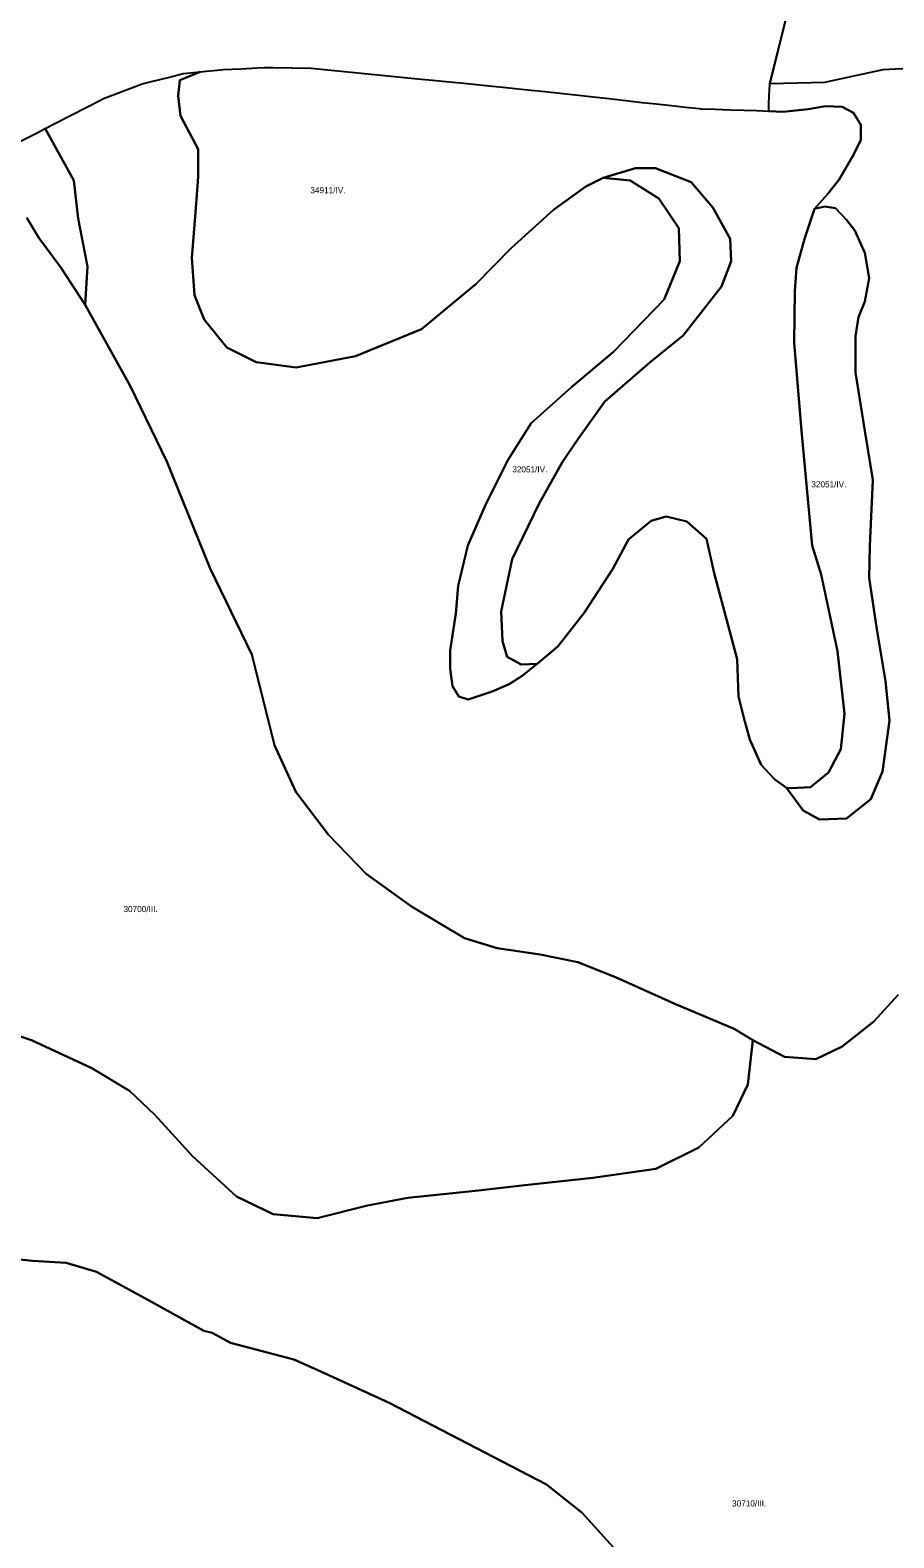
# Model space of a CAD drawing. Extents: x -521621 to -516761, y -1190184 to -1184927.
# Drawn here: x -521195 to -520631, y -1188092 to -1187109 of the extents above; entities that cross this region are included whole.
import ezdxf

# ---------------------------------------------------------------- set-up
doc = ezdxf.new("R2010")
doc.units = 0
doc.layers.add('BPEJ_s', color=7, linetype='Continuous')
doc.layers.add('odvodneni_s', color=7, linetype='Continuous')

msp = doc.modelspace()

# ---------------------------------------------------------------- linework, layer by layer
at = {"layer": 'BPEJ_s'}
for p, q in [((-520712.14, -1187143.85), (-520696.62, -1187081.22)), ((-521116.43, -1187142.72), (-521104.67, -1187139.74)), ((-521104.67, -1187139.74), (-521094.94, -1187137.28)), ((-521083.86, -1187136.13), (-521097.14, -1187141.62)), ((-521094.94, -1187137.28), (-521092.47, -1187137.03)), ((-521092.47, -1187137.03), (-521083.86, -1187136.13)), ((-521142.41, -1187151.9), (-521129.06, -1187146.84)), ((-521129.06, -1187146.84), (-521121.76, -1187144.07)), ((-521121.76, -1187144.07), (-521116.43, -1187142.72)), ((-521097.14, -1187141.62), (-521098.28, -1187151.84)), ((-520712.39, -1187150.86), (-520712.31, -1187148.77)), ((-520712.31, -1187148.77), (-520712.14, -1187143.85)), ((-521169.68, -1187165.29), (-521155.97, -1187158.25)), ((-521155.97, -1187158.25), (-521150.1, -1187155.24)), ((-521150.1, -1187155.24), (-521146.86, -1187153.58)), ((-521146.86, -1187153.58), (-521142.41, -1187151.9)), ((-521098.28, -1187151.84), (-521096.58, -1187164.9)), ((-520712.78, -1187161.74), (-520712.69, -1187159.3)), ((-520712.69, -1187159.3), (-520712.61, -1187156.91)), ((-520712.61, -1187156.91), (-520712.44, -1187152.21)), ((-520712.44, -1187152.21), (-520712.39, -1187150.86)), ((-520675.8, -1187158.53), (-520687.06, -1187160.54)), ((-520664.83, -1187158.92), (-520675.8, -1187158.53)), ((-520657.39, -1187162.84), (-520664.83, -1187158.92)), ((-521184.92, -1187173.11), (-521169.68, -1187165.29)), ((-521096.58, -1187164.9), (-521085.23, -1187186.48)), ((-520703.28, -1187162.15), (-520712.78, -1187161.74)), ((-520687.06, -1187160.54), (-520703.28, -1187162.15)), ((-520652.69, -1187170.68), (-520657.39, -1187162.84)), ((-521166.37, -1187206.92), (-521184.92, -1187173.11)), ((-520652.69, -1187180.48), (-520652.69, -1187170.68)), ((-521085.23, -1187186.48), (-521085.23, -1187204.65)), ((-520657.39, -1187190.28), (-520652.69, -1187180.48)), ((-520666.79, -1187206.35), (-520657.39, -1187190.28)), ((-521163.54, -1187231.9), (-521166.37, -1187206.92)), ((-521085.23, -1187204.65), (-521086.93, -1187227.93)), ((-520832.13, -1187210.89), (-520820.78, -1187205.21)), ((-520820.78, -1187205.21), (-520803.19, -1187206.92)), ((-520803.19, -1187206.92), (-520784.47, -1187218.84)), ((-520674.23, -1187215.75), (-520666.79, -1187206.35)), ((-520853.13, -1187226.22), (-520832.13, -1187210.89)), ((-520784.47, -1187218.84), (-520771.41, -1187238.15)), ((-520682.85, -1187225.55), (-520674.23, -1187215.75)), ((-521086.93, -1187227.93), (-521089.2, -1187257.45)), ((-520880.93, -1187251.21), (-520853.13, -1187226.22)), ((-520676.19, -1187223.98), (-520682.85, -1187225.55)), ((-520669.14, -1187225.16), (-520676.19, -1187223.98)), ((-520662.09, -1187232.61), (-520669.14, -1187225.16)), ((-521157.3, -1187263.13), (-521163.54, -1187231.9)), ((-520771.41, -1187238.15), (-520770.85, -1187259.72)), ((-520656.61, -1187239.66), (-520662.09, -1187232.61)), ((-520649.95, -1187254.16), (-520656.61, -1187239.66)), ((-521089.2, -1187257.45), (-521087.5, -1187281.87)), ((-520903.63, -1187274.49), (-520880.93, -1187251.21)), ((-520647.21, -1187270.62), (-520649.95, -1187254.16)), ((-521159, -1187288.11), (-521157.3, -1187263.13)), ((-520770.85, -1187259.72), (-520781.06, -1187284.71)), ((-520939.39, -1187304.01), (-520903.63, -1187274.49)), ((-520649.95, -1187285.91), (-520647.21, -1187270.62)), ((-521087.5, -1187281.87), (-521081.25, -1187297.77)), ((-520781.06, -1187284.71), (-520813.97, -1187318.78)), ((-520654.26, -1187296.1), (-520649.95, -1187285.91)), ((-521129.49, -1187340.92), (-521159, -1187288.11)), ((-520656.21, -1187308.64), (-520654.26, -1187296.1)), ((-521081.25, -1187297.77), (-521066.5, -1187315.94)), ((-520982.51, -1187321.62), (-520939.39, -1187304.01)), ((-521066.5, -1187315.94), (-521047.21, -1187325.59)), ((-520656.21, -1187332.16), (-520656.21, -1187308.64)), ((-521047.21, -1187325.59), (-521021.1, -1187329)), ((-521021.1, -1187329), (-520982.51, -1187321.62)), ((-520813.97, -1187318.78), (-520841.21, -1187341.49)), ((-520649.95, -1187370.18), (-520656.21, -1187332.16)), ((-521105.66, -1187390.32), (-521129.49, -1187340.92)), ((-520841.21, -1187341.49), (-520867.88, -1187365.34)), ((-520867.88, -1187365.34), (-520883.01, -1187389.38)), ((-520644.86, -1187402.32), (-520649.95, -1187370.18)), ((-521077.32, -1187460.13), (-521105.66, -1187390.32)), ((-520883.01, -1187389.38), (-520897.5, -1187418)), ((-520646.81, -1187445.43), (-520644.86, -1187402.32)), ((-520897.5, -1187418), (-520909.25, -1187445.04)), ((-520804.28, -1187441.12), (-520789.39, -1187428.97)), ((-520789.39, -1187428.97), (-520779.6, -1187426.23)), ((-520779.6, -1187426.23), (-520766.28, -1187429.36)), ((-520766.28, -1187429.36), (-520753.36, -1187440.73)), ((-520909.25, -1187445.04), (-520915.52, -1187471.3)), ((-520814.46, -1187460.33), (-520804.28, -1187441.12)), ((-520753.36, -1187440.73), (-520748.27, -1187463.07)), ((-520647.21, -1187466.2), (-520646.81, -1187445.43)), ((-521050.19, -1187516.05), (-521077.32, -1187460.13)), ((-520833.26, -1187488.94), (-520814.46, -1187460.33)), ((-520748.27, -1187463.07), (-520733.38, -1187519.12)), ((-520915.52, -1187471.3), (-520917.09, -1187489.33)), ((-520642.11, -1187499.52), (-520647.21, -1187466.2)), ((-520917.09, -1187489.33), (-520920.61, -1187513.63)), ((-520850.5, -1187510.89), (-520833.26, -1187488.94)), ((-520636.63, -1187533.62), (-520642.11, -1187499.52)), ((-520920.61, -1187513.63), (-520920.61, -1187525.39)), ((-520863.82, -1187522.25), (-520850.5, -1187510.89)), ((-521035.4, -1187575.26), (-521050.19, -1187516.05)), ((-520873.61, -1187530.09), (-520863.82, -1187522.25)), ((-520733.38, -1187519.12), (-520732.6, -1187543.42)), ((-520920.61, -1187525.39), (-520919.05, -1187536.75)), ((-520882.23, -1187535.58), (-520873.61, -1187530.09)), ((-520919.05, -1187536.75), (-520915.13, -1187543.42)), ((-520908.86, -1187545.38), (-520893.19, -1187540.28)), ((-520893.19, -1187540.28), (-520882.23, -1187535.58)), ((-520633.89, -1187559.09), (-520636.63, -1187533.62)), ((-520915.13, -1187543.42), (-520908.86, -1187545.38)), ((-520732.6, -1187543.42), (-520728.29, -1187559.88)), ((-520728.29, -1187559.88), (-520725.15, -1187571.64)), ((-520638.59, -1187592.41), (-520633.89, -1187559.09)), ((-520725.15, -1187571.64), (-520717.71, -1187588.1)), ((-521021.43, -1187605.69), (-521035.4, -1187575.26)), ((-520717.71, -1187588.1), (-520709.09, -1187597.5)), ((-520646.03, -1187610.44), (-520638.59, -1187592.41)), ((-520709.09, -1187597.5), (-520701.26, -1187602.99)), ((-521000.06, -1187633.65), (-521021.43, -1187605.69)), ((-520701.26, -1187602.99), (-520690.29, -1187617.89)), ((-520662.09, -1187622.98), (-520646.03, -1187610.44)), ((-520690.29, -1187617.89), (-520679.72, -1187623.76)), ((-520679.72, -1187623.76), (-520662.09, -1187622.98)), ((-520975.4, -1187659.15), (-521000.06, -1187633.65)), ((-520945.81, -1187680.53), (-520975.4, -1187659.15)), ((-520911.29, -1187701.09), (-520945.81, -1187680.53)), ((-520889.93, -1187707.67), (-520911.29, -1187701.09)), ((-520861.98, -1187711.78), (-520889.93, -1187707.67)), ((-520837.32, -1187716.72), (-520861.98, -1187711.78)), ((-520812.67, -1187726.58), (-520837.32, -1187716.72)), ((-520774.04, -1187743.85), (-520812.67, -1187726.58)), ((-520628.29, -1187738.12), (-520644.18, -1187755.37)), ((-520735.41, -1187760.3), (-520774.04, -1187743.85)), ((-520644.18, -1187755.37), (-520664.73, -1187771.82)), ((-520723.08, -1187767.71), (-520735.41, -1187760.3)), ((-520702.53, -1187778.4), (-520723.08, -1187767.71)), ((-520681.99, -1187780.04), (-520702.53, -1187778.4)), ((-520664.73, -1187771.82), (-520681.99, -1187780.04))]:
    msp.add_line(p, q, dxfattribs=at)
for points in [[(-521083.86, -1187136.13), (-521079.87, -1187135.72), (-521070.36, -1187134.74), (-521068.74, -1187134.66), (-521057.08, -1187134.09), (-521046.69, -1187133.59), (-521042.18, -1187133.37), (-521036.43, -1187133.43), (-521011.32, -1187133.7), (-520941.75, -1187140.65), (-520932.28, -1187141.59), (-520923.44, -1187142.47), (-520914.04, -1187143.41), (-520905.54, -1187144.26), (-520895.29, -1187145.28), (-520886.24, -1187146.19), (-520876.38, -1187147.17), (-520867.83, -1187148.09), (-520858.82, -1187149.08), (-520848.97, -1187150.16), (-520815.24, -1187153.86), (-520804.3, -1187155.06), (-520795.33, -1187156.04), (-520786.18, -1187157.04), (-520776.33, -1187158.12), (-520767.17, -1187159.13), (-520758.16, -1187160.11), (-520757, -1187160.24), (-520747.8, -1187160.55), (-520737.71, -1187160.89), (-520728.89, -1187161.19), (-520720.83, -1187161.47), (-520712.78, -1187161.74), (-520703.28, -1187162.15), (-520687.06, -1187160.54), (-520675.8, -1187158.53), (-520664.83, -1187158.92), (-520657.39, -1187162.84), (-520652.69, -1187170.68), (-520652.69, -1187180.48), (-520657.39, -1187190.28), (-520666.79, -1187206.35), (-520674.23, -1187215.75), (-520682.85, -1187225.55), (-520689.12, -1187244.36), (-520694.6, -1187263.96), (-520695.78, -1187279.25), (-520696.17, -1187312.56), (-520691.47, -1187370.18), (-520684.42, -1187445.04), (-520678.54, -1187463.85), (-520667.97, -1187514.02), (-520663.27, -1187554.78), (-520665.62, -1187577.91), (-520673.84, -1187593.19), (-520685.59, -1187602.6), (-520698.13, -1187603.38), (-520701.26, -1187602.99), (-520709.09, -1187597.5), (-520717.71, -1187588.1), (-520725.15, -1187571.64), (-520728.29, -1187559.88), (-520732.6, -1187543.42), (-520733.38, -1187519.12), (-520748.27, -1187463.07), (-520753.36, -1187440.73), (-520766.28, -1187429.36), (-520779.6, -1187426.23), (-520789.39, -1187428.97), (-520804.28, -1187441.12), (-520814.46, -1187460.33), (-520833.26, -1187488.94), (-520850.5, -1187510.89), (-520863.82, -1187522.25), (-520874.39, -1187522.64), (-520883.4, -1187517.55), (-520886.54, -1187507.36), (-520887.32, -1187488.15), (-520880.27, -1187454.05), (-520862.64, -1187417.6), (-520847.37, -1187390.56), (-520837.24, -1187375.56), (-520819.65, -1187351.14), (-520790.14, -1187325.59), (-520768.58, -1187307.99), (-520743.61, -1187276.19), (-520737.36, -1187259.72), (-520737.93, -1187244.96), (-520749.28, -1187224.52), (-520763.47, -1187208.05), (-520786.74, -1187198.97), (-520799.79, -1187198.97), (-520820.78, -1187205.21), (-520832.13, -1187210.89), (-520853.13, -1187226.22), (-520880.93, -1187251.21), (-520903.63, -1187274.49), (-520939.39, -1187304.01), (-520982.51, -1187321.62), (-521021.1, -1187329), (-521047.21, -1187325.59), (-521066.5, -1187315.94), (-521081.25, -1187297.77), (-521087.5, -1187281.87), (-521089.2, -1187257.45), (-521086.93, -1187227.93), (-521085.23, -1187204.65), (-521085.23, -1187186.48), (-521096.58, -1187164.9), (-521098.28, -1187151.84), (-521097.14, -1187141.62)], [(-520863.82, -1187522.25), (-520873.61, -1187530.09), (-520882.23, -1187535.58), (-520893.19, -1187540.28), (-520908.86, -1187545.38), (-520915.13, -1187543.42), (-520919.05, -1187536.75), (-520920.61, -1187525.39), (-520920.61, -1187513.63), (-520917.09, -1187489.33), (-520915.52, -1187471.3), (-520909.25, -1187445.04), (-520897.5, -1187418), (-520883.01, -1187389.38), (-520867.88, -1187365.34), (-520841.21, -1187341.49), (-520813.97, -1187318.78), (-520781.06, -1187284.71), (-520770.85, -1187259.72), (-520771.41, -1187238.15), (-520784.47, -1187218.84), (-520803.19, -1187206.92), (-520820.78, -1187205.21), (-520799.79, -1187198.97), (-520786.74, -1187198.97), (-520763.47, -1187208.05), (-520749.28, -1187224.52), (-520737.93, -1187244.96), (-520737.36, -1187259.72), (-520743.61, -1187276.19), (-520768.58, -1187307.99), (-520790.14, -1187325.59), (-520819.65, -1187351.14), (-520837.24, -1187375.56), (-520847.37, -1187390.56), (-520862.64, -1187417.6), (-520880.27, -1187454.05), (-520887.32, -1187488.15), (-520886.54, -1187507.36), (-520883.4, -1187517.55), (-520874.39, -1187522.64)], [(-520701.26, -1187602.99), (-520698.13, -1187603.38), (-520685.59, -1187602.6), (-520673.84, -1187593.19), (-520665.62, -1187577.91), (-520663.27, -1187554.78), (-520667.97, -1187514.02), (-520678.54, -1187463.85), (-520684.42, -1187445.04), (-520691.47, -1187370.18), (-520696.17, -1187312.56), (-520695.78, -1187279.25), (-520694.6, -1187263.96), (-520689.12, -1187244.36), (-520682.85, -1187225.55), (-520676.19, -1187223.98), (-520669.14, -1187225.16), (-520662.09, -1187232.61), (-520656.61, -1187239.66), (-520649.95, -1187254.16), (-520647.21, -1187270.62), (-520649.95, -1187285.91), (-520654.26, -1187296.1), (-520656.21, -1187308.64), (-520656.21, -1187332.16), (-520649.95, -1187370.18), (-520644.86, -1187402.32), (-520646.81, -1187445.43), (-520647.21, -1187466.2), (-520642.11, -1187499.52), (-520636.63, -1187533.62), (-520633.89, -1187559.09), (-520638.59, -1187592.41), (-520646.03, -1187610.44), (-520662.09, -1187622.98), (-520679.72, -1187623.76), (-520690.29, -1187617.89)]]:
    msp.add_lwpolyline(points, close=True, dxfattribs=at)
for points in [[(-521212.57, -1187187.3), (-521191.12, -1187176.3), (-521184.92, -1187173.11), (-521166.37, -1187206.92), (-521163.54, -1187231.9), (-521157.3, -1187263.13), (-521159, -1187288.11), (-521174.89, -1187263.7), (-521189.07, -1187244.39), (-521197.02, -1187231.33)], [(-521197.02, -1187231.33), (-521189.07, -1187244.39), (-521174.89, -1187263.7), (-521159, -1187288.11), (-521129.49, -1187340.92), (-521105.66, -1187390.32), (-521077.32, -1187460.13), (-521050.19, -1187516.05), (-521035.4, -1187575.26), (-521021.43, -1187605.69), (-521000.06, -1187633.65), (-520975.4, -1187659.15), (-520945.81, -1187680.53), (-520911.29, -1187701.09), (-520889.93, -1187707.67), (-520861.98, -1187711.78), (-520837.32, -1187716.72), (-520812.67, -1187726.58), (-520774.04, -1187743.85), (-520735.41, -1187760.3), (-520723.08, -1187767.71), (-520726.37, -1187796.49), (-520736.23, -1187817.05), (-520758.42, -1187837.61), (-520786.37, -1187851.59), (-520827.46, -1187857.35), (-520871.84, -1187862.28), (-520902.25, -1187865.57), (-520948.28, -1187870.5), (-520974.58, -1187875.44), (-521007.46, -1187883.66), (-521036.22, -1187881.2), (-521060.06, -1187869.68), (-521088.82, -1187843.36), (-521113.48, -1187816.23), (-521129.92, -1187800.6), (-521154.57, -1187785.8), (-521194.03, -1187767.71), (-521228.54, -1187756.19)], [(-521228.54, -1187756.19), (-521194.03, -1187767.71), (-521154.57, -1187785.8), (-521129.92, -1187800.6), (-521113.48, -1187816.23), (-521088.82, -1187843.36), (-521060.06, -1187869.68), (-521036.22, -1187881.2), (-521007.46, -1187883.66), (-520974.58, -1187875.44), (-520948.28, -1187870.5), (-520902.25, -1187865.57), (-520871.84, -1187862.28), (-520827.46, -1187857.35), (-520786.37, -1187851.59), (-520758.42, -1187837.61), (-520736.23, -1187817.05), (-520726.37, -1187796.49), (-520723.08, -1187767.71), (-520702.53, -1187778.4), (-520681.99, -1187780.04), (-520664.73, -1187771.82), (-520644.18, -1187755.37), (-520628.29, -1187738.12)], [(-520804.04, -1188109.66), (-520834.55, -1188075.81), (-520857.72, -1188057.36), (-520960.58, -1188004.1), (-521007.45, -1187982.73), (-521022.67, -1187975.86), (-521064.14, -1187965.05), (-521075.92, -1187958.42), (-521081.56, -1187957.19), (-521115.69, -1187938.25), (-521151.49, -1187918.7), (-521171.39, -1187912.91), (-521193.22, -1187911.63), (-521229.18, -1187907.77)], [(-521229.18, -1187907.77), (-521193.22, -1187911.63), (-521171.39, -1187912.91), (-521151.49, -1187918.7), (-521115.69, -1187938.25), (-521081.56, -1187957.19), (-521075.92, -1187958.42), (-521064.14, -1187965.05), (-521022.67, -1187975.86), (-521007.45, -1187982.73), (-520960.58, -1188004.1), (-520857.72, -1188057.36), (-520834.55, -1188075.81), (-520804.04, -1188109.66)]]:
    msp.add_lwpolyline(points, dxfattribs=at)
at = {"layer": 'odvodneni_s'}
msp.add_lwpolyline([(-520696.62, -1187081.22), (-520712.14, -1187143.85), (-520676.24, -1187142.96), (-520637.97, -1187134.59), (-520626.08, -1187134.07), (-520549.68, -1187152.94), (-520522.41, -1187154.49), (-520507.8, -1187156.82), (-520488.41, -1187163.67), (-520391.84, -1187190.3), (-520367.93, -1187195.08), (-520338.85, -1187197.93), (-520302, -1187205.94), (-520280.02, -1187212.1), (-520239.28, -1186854.88)], dxfattribs=at)

# ---------------------------------------------------------------- texts
at = {"layer": 'BPEJ_s'}
for s, p in [('34911/IV.', (-521011.89, -1187215.33)), ('32051/IV.', (-520880.14, -1187397.37)), ('32051/IV.', (-520684.96, -1187407.13)), ('30700/III.', (-521133.88, -1187684.13)), ('30710/III.', (-520736.67, -1188071.75))]:
    msp.add_text(s, height=4, dxfattribs=at).set_placement(p)

doc.saveas('drawing.dxf')
